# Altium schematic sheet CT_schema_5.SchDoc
size 274 x 160 mm
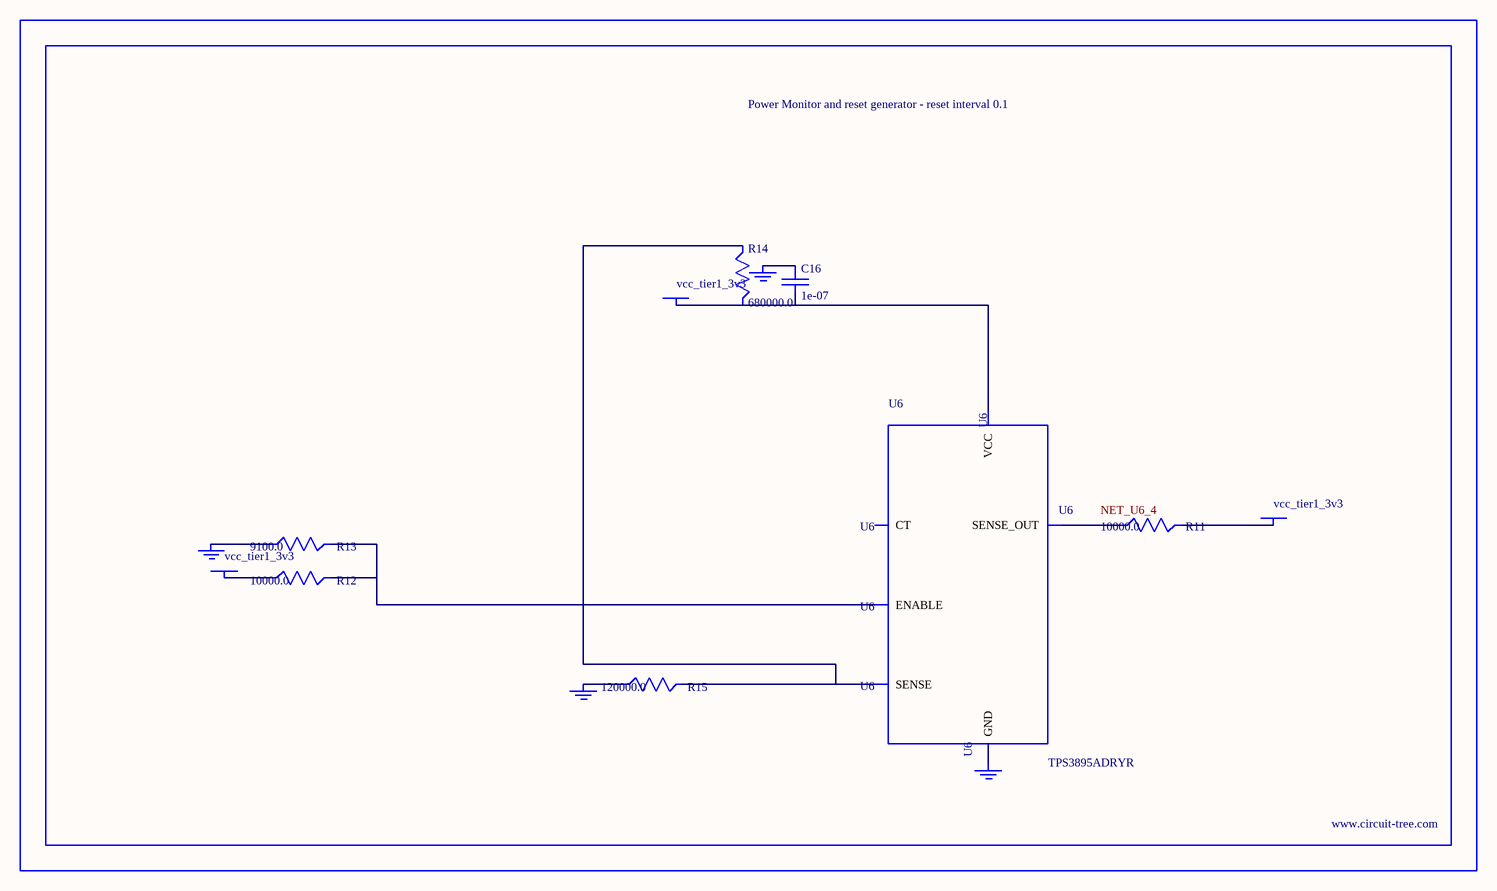
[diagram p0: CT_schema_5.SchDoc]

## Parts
BORDER4  (no value)
C16  1e-07  [C0402]
GND_INSTANCE_4_0  (no value)
GND_INSTANCE_4_1  (no value)
GND_INSTANCE_4_2  (no value)
GND_INSTANCE_4_3  (no value)
POWER_INSTANCE_4_0  vcc_tier1_3v3
POWER_INSTANCE_4_1  vcc_tier1_3v3
POWER_INSTANCE_4_2  vcc_tier1_3v3
R11  10000.0  [R0603]
R12  10000.0  [R0603]
R13  9100.0  [R0603]
R14  680000.0  [R0603]
R15  120000.0  [R0603]
U6  TPS3895ADRYR  [SON-6]

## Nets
NetC16_1: C16.1 GND_INSTANCE_4_2.0(GND)
NetC16_2: C16.2 POWER_INSTANCE_4_2.0(PWR) R14.2 U6.6(VCC)
NetGND_INSTANCE_4_0_0: GND_INSTANCE_4_0.0(GND) R13.1
NetGND_INSTANCE_4_1_0: GND_INSTANCE_4_1.0(GND) R15.1
NetGND_INSTANCE_4_3_0: GND_INSTANCE_4_3.0(GND) U6.2(GND)
NetPOWER_INSTANCE_4_0_0: POWER_INSTANCE_4_0.0(PWR) R12.1
NetPOWER_INSTANCE_4_1_0: POWER_INSTANCE_4_1.0(PWR) R11.2
NetR11_1: R11.1 U6.4(SENSE_OUT)
NetR12_2: R12.2 R13.2 U6.1(ENABLE)
NetR14_1: R14.1 R15.2 U6.3(SENSE)

Not connected (* = marked no-connect by the designer): U6 5(CT)

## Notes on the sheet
- Labels drawn without touching a wire or pin: NET_U6_4

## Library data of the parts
BORDER4 = BORDER_PAGE4
C16 = C0402C104K3RACTU
GND_INSTANCE_4_0-GND_INSTANCE_4_3 = GND
POWER_INSTANCE_4_0-POWER_INSTANCE_4_2 = PWR
R11 R12 = RC0603JR-0710KL
R13 = RC0603JR-079K1L
R14 = RC0603JR-07680KL
R15 = RC0603JR-07120KL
